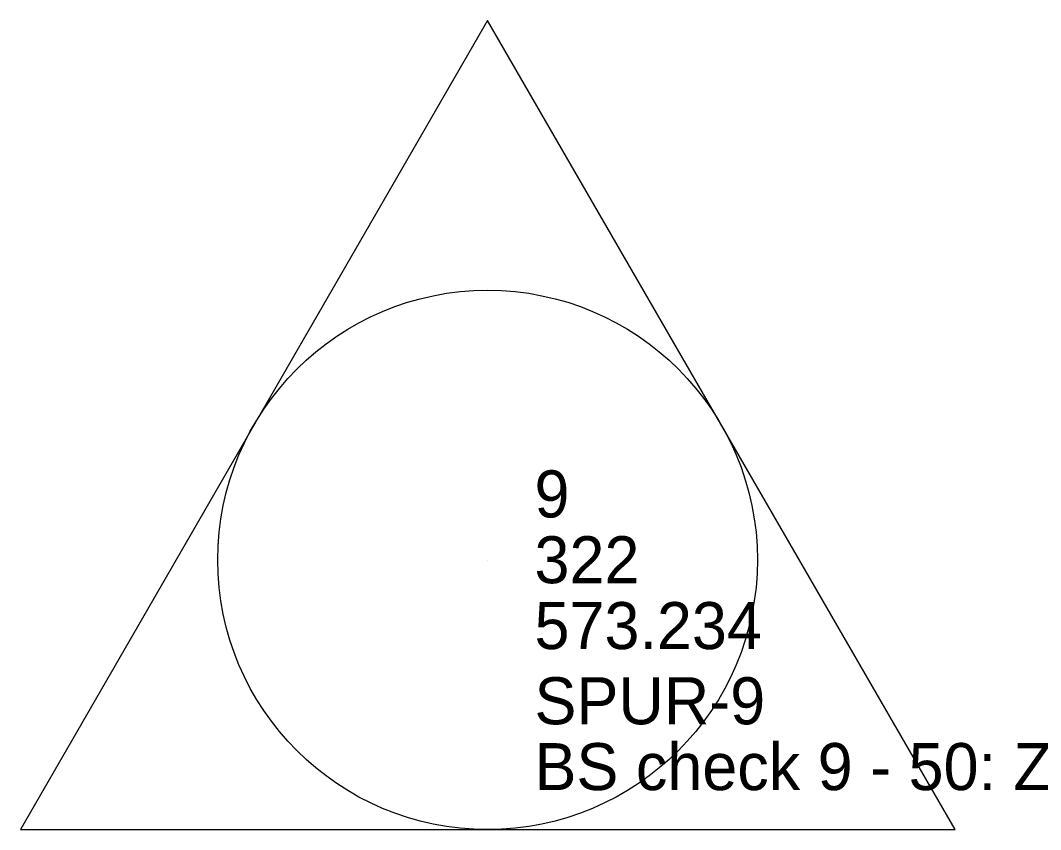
# Model space of a CAD drawing. Extents: x 5447 to 709667, y 4528 to 375505.
# Drawn here: x 708517.6 to 708523.02, y 374451.5 to 374455.8 of the extents above; entities that cross this region are included whole.
import ezdxf

# ---------------------------------------------------------------- set-up
doc = ezdxf.new("R2010")
doc.units = 0
for name, color, linetype in [('SV_CTRL_CPT', 7, 'Continuous'), ('SV_NODES_DESCRIPTION', 7, 'Continuous'), ('SV_NODES_ELEVATION', 7, 'Continuous'), ('SV_NODES_PT_NUMBER', 7, 'Continuous'), ('SV_SURVEY_NOTES', 7, 'Continuous')]:
    doc.layers.add(name, color=color, linetype=linetype)

msp = doc.modelspace()

# ---------------------------------------------------------------- linework, layer by layer
at = {"layer": 'SV_CTRL_CPT'}
for p, q in [((708520.083, 374455.802), (708517.601, 374451.499)), ((708522.568, 374451.499), (708520.083, 374455.802)), ((708520.083, 374452.932), (708520.083, 374452.932)), ((708517.601, 374451.499), (708522.568, 374451.499))]:
    msp.add_line(p, q, dxfattribs=at)
msp.add_circle((708520.0838, 374452.9333), 1.434, dxfattribs=at)

# ---------------------------------------------------------------- texts
at = {"layer": 'SV_NODES_DESCRIPTION'}
msp.add_text('322', height=0.25, dxfattribs=at).set_placement((708520.333, 374452.809))
msp.add_text('322', height=0.25, dxfattribs=at).set_placement((708520.333, 374452.809))
msp.add_text('322', height=0.25, dxfattribs=at).set_placement((708520.333, 374452.809))
at = {"layer": 'SV_NODES_ELEVATION'}
msp.add_text('573.234', height=0.25, dxfattribs=at).set_placement((708520.333, 374452.459))
msp.add_text('573.234', height=0.25, dxfattribs=at).set_placement((708520.333, 374452.459))
msp.add_text('573.234', height=0.25, dxfattribs=at).set_placement((708520.333, 374452.459))
at = {"layer": 'SV_NODES_PT_NUMBER'}
msp.add_text('9', height=0.25, dxfattribs=at).set_placement((708520.333, 374453.159))
msp.add_text('9', height=0.25, dxfattribs=at).set_placement((708520.333, 374453.159))
msp.add_text('9', height=0.25, dxfattribs=at).set_placement((708520.333, 374453.159))
at = {"layer": 'SV_SURVEY_NOTES'}
for s, p in [('SPUR-9', (708520.333, 374452.059)), ('SPUR-9', (708520.333, 374452.059)), ('SPUR-9', (708520.333, 374452.059)), ('BS check 9 - 50: ZE94.1444,SD163.090,HD err= -0.003, VD err= -0.020', (708520.333, 374451.709)), ('BS check 9 - 50: ZE94.1444,SD163.090,HD err= -0.003, VD err= -0.020', (708520.333, 374451.709)), ('BS check 9 - 50: ZE94.1444,SD163.090,HD err= -0.003, VD err= -0.020', (708520.333, 374451.709))]:
    msp.add_text(s, height=0.25, dxfattribs=at).set_placement(p)

doc.saveas('drawing.dxf')
